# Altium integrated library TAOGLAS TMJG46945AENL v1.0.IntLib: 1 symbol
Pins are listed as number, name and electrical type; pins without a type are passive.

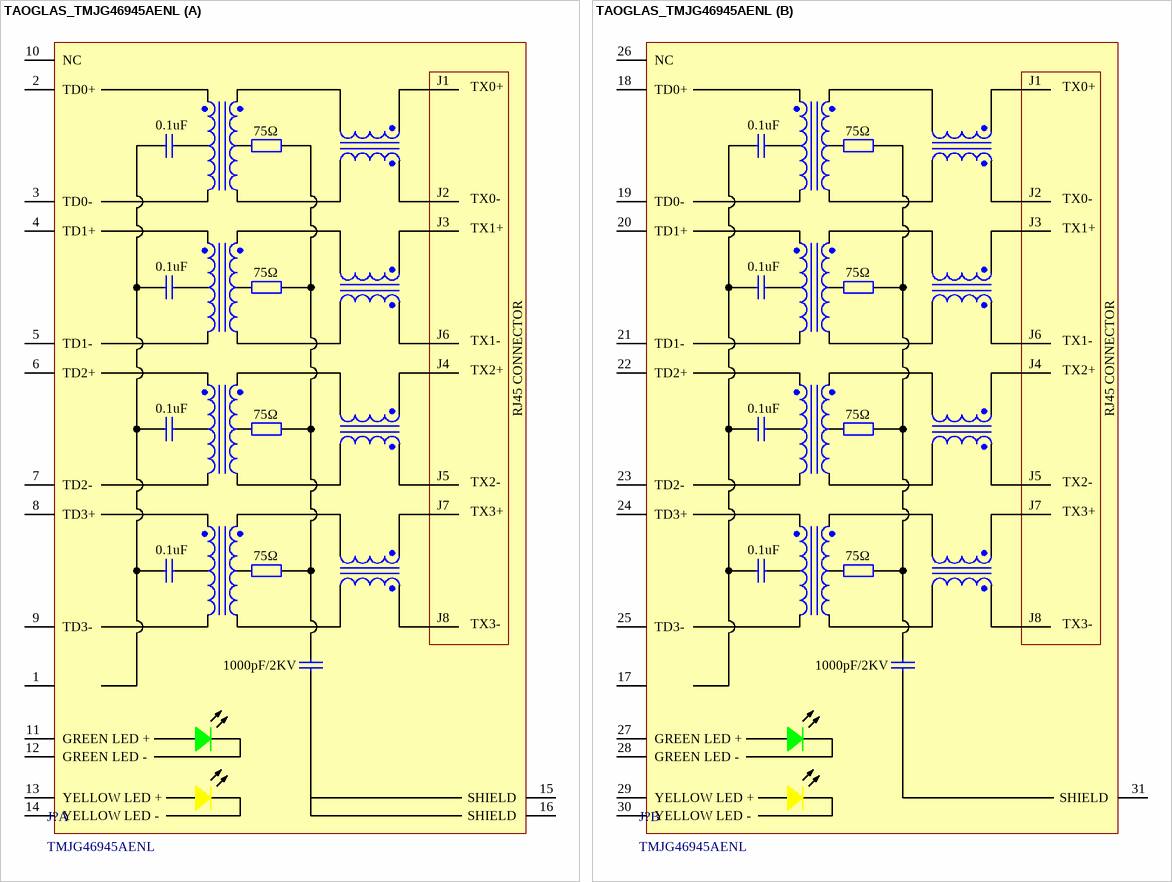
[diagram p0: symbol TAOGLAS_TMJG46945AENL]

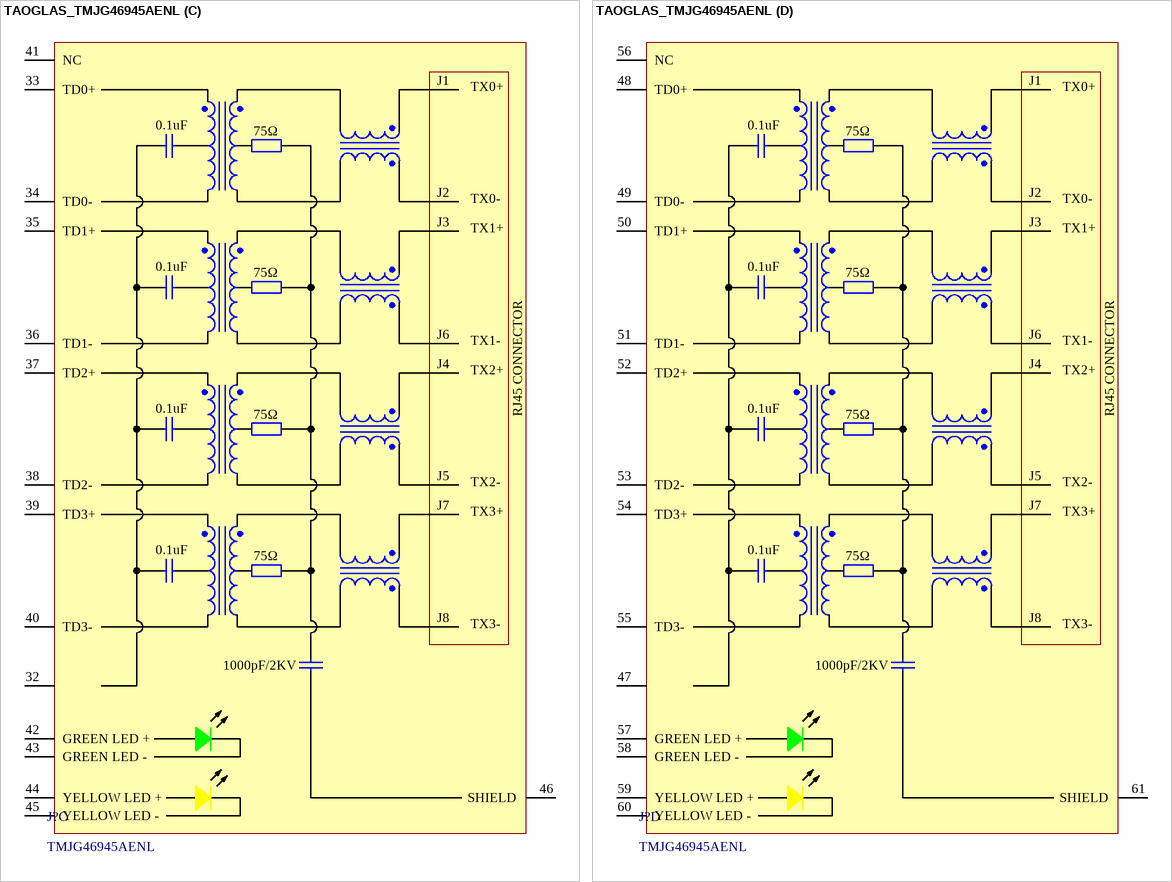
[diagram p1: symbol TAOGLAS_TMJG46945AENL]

## TAOGLAS_TMJG46945AENL
designator J?, comment TMJG46945AENL
RJ45 Connector, 1000Base-T, 1x4 Ports, Down, Shielded W/LED, THT, Industrial grade; ComponentLibStatus: Created; MFG: Taoglas; Temp_High: +85C; Temp_Low: -40C
footprint TAOGLAS_TMJG46945AENL (RJ45 Connector, 1000Base-T, 1x4 Ports, Down, Shielded W/LED, THT, Industrial grade)
part A pins: 1, 2 TD0+, 3 TD0-, 4 TD1+, 5 TD1-, 6 TD2+, 7 TD2-, 8 TD3+, 9 TD3-, 10 NC, 11 GREEN LED +, 12 GREEN LED -, 13 YELLOW LED +, 14 YELLOW LED -, 15 SHIELD, 16 SHIELD
part B pins: 17, 18 TD0+, 19 TD0-, 20 TD1+, 21 TD1-, 22 TD2+, 23 TD2-, 24 TD3+, 25 TD3-, 26 NC, 27 GREEN LED +, 28 GREEN LED -, 29 YELLOW LED +, 30 YELLOW LED -, 31 SHIELD
part C pins: 32, 33 TD0+, 34 TD0-, 35 TD1+, 36 TD1-, 37 TD2+, 38 TD2-, 39 TD3+, 40 TD3-, 41 NC, 42 GREEN LED +, 43 GREEN LED -, 44 YELLOW LED +, 45 YELLOW LED -, 46 SHIELD
part D pins: 47, 48 TD0+, 49 TD0-, 50 TD1+, 51 TD1-, 52 TD2+, 53 TD2-, 54 TD3+, 55 TD3-, 56 NC, 57 GREEN LED +, 58 GREEN LED -, 59 YELLOW LED +, 60 YELLOW LED -, 61 SHIELD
